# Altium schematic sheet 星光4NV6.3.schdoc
size 292 x 204 mm; Device: A_A4_1; Symbol: A_A4_1; Name: A_A4; @Project Name: 星光4N开源6.1版本; REV: 6.1; Date: 2025/11/29; Sheet: 1/1; Draw By: 韩; Company: 流浪的星星; Convert to PCB: yes; Add into BOM: yes; @Page No: 1; @Page Count: 1; @Schematic Name: 星光4NV6.1; @Board Name: 星光4NV6.1; @Update Date: 2025-11-29; @Create Time: 10:46:54; @Update Time: 11:45:03; @Page Name: 星光4奥卡; @Create Date: 2025-11-29; Border: 0; Width: 1655; Height: 1170; Region Start: 1; X Region Count: 1; Y Region Count: 1; Title Block Position: 3; Title Block: 1
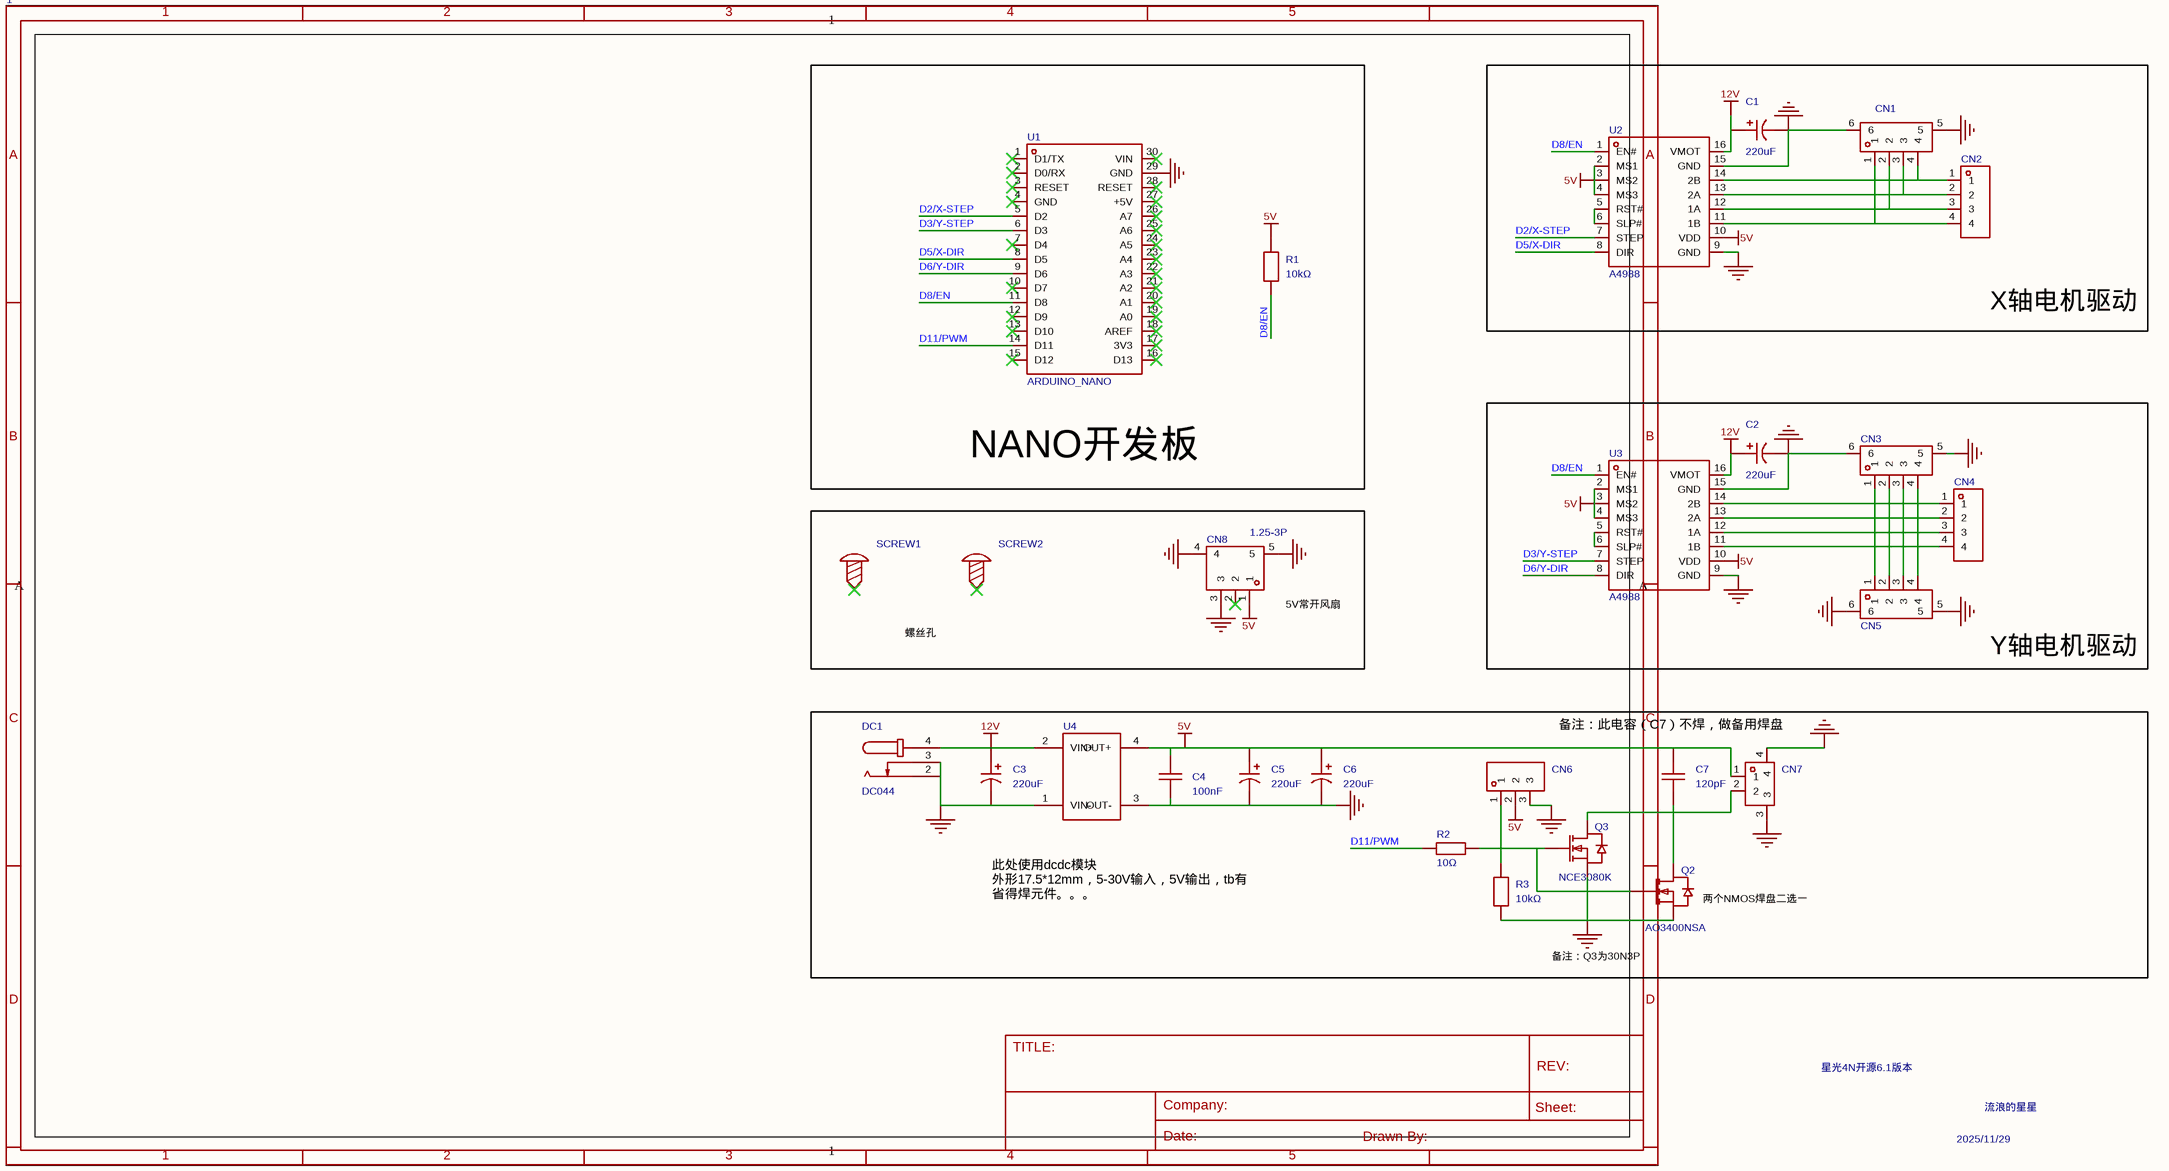
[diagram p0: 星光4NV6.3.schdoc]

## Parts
C1  220uF  [CAP-SMD_BD6.3-L6.6-W6.6-FD-1]
C2  220uF  [CAP-SMD_BD6.3-L6.6-W6.6-FD-1]
C3  220uF  [CAP-SMD_BD6.3-L6.6-W6.6-FD-1]
C4  100nF  [C1206]
C5  220uF  [CAP-SMD_BD6.3-L6.6-W6.6-FD-1]
C6  220uF  [CAP-SMD_BD6.3-L6.6-W6.6-FD-1]
C7  120pF  [C1812]
CN1  AFA07-S04ECC-00  [FPC-SMD_4P-P1.00_AFA07-S04ECC-00]  (value not drawn)
CN2  2.54-1*4P母  [HDR-TH_4P-P2.54-V-F]  (value not drawn)
CN3  10A20L04P  [FPC-SMD_4P-P1.00_10A20L04P]  (value not drawn)
CN4  2.54-1*4P母  [HDR-TH_4P-P2.54-V-F]  (value not drawn)
CN5  10A20L04P  [FPC-SMD_4P-P1.00_10A20L04P]  (value not drawn)
CN6  ZX-XH2.54-3PWZ  [HDR-TH_3P-P2.50_ZX-XH2.54-3PWZ]  (value not drawn)
CN7  ZX-XH2.54-2PWT  [CONN-SMD_2P-P2.54_MEGASTAR_ZX-XH2.54-2PWT]  (value not drawn)
CN8  1.25-3P  [CONN-SMD_1.25-3P]
DC1  DC044  [DC-IN-TH_DC044]
Q2  AO3400NSA  [SOT-23-3_L2.9-W1.3-P1.90-LS2.4-BR]
Q3  NCE3080K  [TO-252-2_L6.6-W6.1-P4.57-LS9.9-TL-CW]
R1  10kΩ  [R1206]
R2  10Ω  [R1206]
R3  10kΩ  [R1206]
SCREW1  (no value)  [M3螺丝]
SCREW2  (no value)  [M3螺丝]
U1  ARDUINO_NANO  [COMM-TH_ARDUINO_NANO]
U2  A4988  [DIP-16_L20.3-W15.2-P2.54_LS12.7_A4988]
U3  A4988  [DIP-16_L20.3-W15.2-P2.54_LS12.7_A4988]
U4  (no value)  [迷你稳压模块]

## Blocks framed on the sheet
NANO开发板: R1 U1
X轴电机驱动: C1 CN1 CN2 U2
Y轴电机驱动: C2 CN3-CN5 U3
备注：此电容（C7）不焊，做备用焊盘: C3-C7 CN6 CN7 DC1 Q2 Q3 R2 R3 U4

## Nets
5V: C4.2 C5.1 C6.1 C7.2 CN6.2 CN7.1 CN8.1 R1.2 U2.2(MS1) U2.3(MS2) U2.4(MS3) U2.10(VDD) U3.2(MS1) U3.3(MS2) U3.4(MS3) U3.10(VDD) U4.4(OUT+)
12V: C1.1 C2.1 C3.1 DC1.4 U2.16(VMOT) U3.16(VMOT) U4.2(VIN+)
GND: C1.2 C2.2 C3.2 C4.1 C5.2 C6.2 CN1.5 CN1.6 CN3.5 CN3.6 CN5.5 CN5.6 CN6.3 CN7.3 CN7.4 CN8.3 CN8.4 CN8.5 DC1.2 DC1.3 Q2.2(S) Q3.3(S) R3.1 U1.29(GND) U2.9(GND) U2.15(GND) U3.9(GND) U3.15(GND) U4.1(VIN-) U4.3(OUT-)
D2/X-STEP: U1.5(D2) U2.7(STEP)
D3/Y-STEP: U1.6(D3) U3.7(STEP)
D5/X-DIR: U1.8(D5) U2.8(DIR)
D6/Y-DIR: U1.9(D6) U3.8(DIR)
D8/EN: R1.1 U1.11(D8) U2.1(EN#) U3.1(EN#)
D11/PWM: R2.2 U1.14(D11)
NetC7_1: C7.1 CN7.2 Q2.3(D) Q3.2(D)
NetCN1_1: CN1.1 CN2.4 U2.11(1B)
NetCN1_2: CN1.2 CN2.3 U2.12(1A)
NetCN1_3: CN1.3 CN2.2 U2.13(2A)
NetCN1_4: CN1.4 CN2.1 U2.14(2B)
NetCN3_1: CN3.1 CN4.4 CN5.1 U3.11(1B)
NetCN3_2: CN3.2 CN4.3 CN5.2 U3.12(1A)
NetCN3_3: CN3.3 CN4.2 CN5.3 U3.13(2A)
NetCN3_4: CN3.4 CN4.1 CN5.4 U3.14(2B)
NetCN6_1: CN6.1 Q2.1(G) Q3.1(G) R2.1 R3.2
NetU2_5: U2.5(RST#) U2.6(SLP#)
NetU3_5: U3.5(RST#) U3.6(SLP#)

Not connected (* = marked no-connect by the designer): CN8 2*; SCREW1 1*; SCREW2 1*; U1 1(D1/TX)* 2(D0/RX)* 3(RESET)* 4(GND)* 7(D4)* 10(D7)* 12(D9)* 13(D10)* 15(D12)* 16(D13)* 17(3V3)* 18(AREF)* 19(A0)* 20(A1)* 21(A2)* 22(A3)* 23(A4)* 24(A5)* 25(A6)* 26(A7)* 27(+5V)* 28(RESET)* 30(VIN)*

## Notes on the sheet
- (near CN8) 5V常开风扇
- 螺丝孔
- 此处使用dcdc模块
  外形17.5*12mm，5-30V输入，5V输出，tb有
  省得焊元件。。。
- (near Q2) 两个NMOS焊盘二选一
- 备注：Q3为30N3P

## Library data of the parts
C1-C3 C5 C6 = JVJ16V220M6x8: 容值:220uF;精度:±20%;额定电压:16V;纹波电流:110mA@120Hz;; Manufacturer: 捷而瑞; AddInBom: yes; ModelId: 041333f082e2432d92aae8a67d233574; ModelTransform: 299.212,259.842,0,0,0,0,0,0,0; Tolerance: ±20%; Voltage Rating: 16V; Lifetime: 2000hrs@105℃
C4 = CL31B104KBCNNNC: 容值:100nF;精度:±10%;额定电压:50V;温度系数:X7R;; Manufacturer: SAMSUNG(三星); AddInBom: yes; ModelId: e4be705b945545a48e666415e3682bd8; ModelName: C1206_L3.2-W1.6-H1.3; ModelTransform: 125.984,62.992,0,0,0,0,0,0,0; Tolerance: ±10%; Voltage Rating: 50V; Temperature Coefficient: X7R
C7 = FV43N121J302ECG: 容值:120pF;精度:±5%;额定电压:3kV;温度系数:C0G;; Manufacturer: PSA(信昌电陶); AddInBom: yes; ModelId: 654205cbd64044c4b833fe7af5979bc9; ModelName: C1812_L4.5-W3.2-H2.6; ModelTransform: 177.165,125.984,0,0,0,0,0.0005,0,0; Tolerance: ±5%; Voltage Rating: 3kV; Temperature Coefficient: C0G
CN1 = AFA07-S04ECC-00: 锁定特性:抽屉式;触点类型:上接;触点数量:4P;间距:1mm;安装类型:卧贴;; Manufacturer: JS(钜硕电子); Symbol: FPCPull type Pick up H3.0mm; AddInBom: yes; ModelId: eb2037eadb4f4f60bc0cbc983aef8acd; ModelName: FPC-SMD_4P-P1.00_L11.0-W6.9-H2.5-AFA07-S04ECC-00; ModelTransform: 433.07,271.653,0,0,0,0,0,-76.773,0; Locking Feature: 抽屉式; Number of Contacts: 4P; Pitch: 1mm; FFC, FCB Thickness: 0.3mm
CN2 CN4 = 2.54-1*4P母: 插孔结构:1x4P;间距:2.54mm;行距:-;圆孔/方孔:方孔;安装类型:直插;排数:单排;总孔位数:4P;额定电流:3A;额定电压:-;插孔方向:顶部;塑高:-;触头材质:青铜;触头镀层:-;工作温度范围:-40℃~+105℃;焊接温度(最大值):-;; Manufacturer: BOOMELE(博穆精密); AddInBom: yes; ModelId: d187812051054f85879fcaa51a310d8e; ModelTransform: 419.6842,98.464,0,0,0,0,0,0,-118.11; Holes Structure: 1x4P; Pitch: 2.54mm; Circular Hole / Square Hole: 方孔; Number of Holes: 4P; Current Rating (Max): 3A; Holes Direction: 顶部
CN3 CN5 = 10A20L04P: 锁定特性:翻盖式;触点类型:下接;触点数量:4P;间距:1mm;; Manufacturer: HanElectricity(瀚源); AddInBom: yes; ModelId: 74aa4c8d5552434e99fa2d5862a4320d; ModelTransform: 354.7237,234.2515,0,0,0,0,0,-62.165,0; Locking Feature: 翻盖式; Number of Contacts: 4P; Pitch: 1mm
CN6 = ZX-XH2.54-3PWZ: 插针结构:1x3P;间距:2.5mm;安装方式:弯插;参考系列:XH;总PIN数:3P;排数:1;每排PIN数:3;行距:-;额定电流:3A;触头材质:黄铜;触头镀层:锡;工作温度:-25℃~+85℃;; Manufacturer: Megastar(兆星); AddInBom: yes; ModelId: a145bc240201499fa30f39acf7784329; ModelTransform: 394.094,300.58995,0,0,0,0,-0.005,-137.792,-133.858; Pins Structure: 1x3P; Pitch: 2.5mm; Reference Series: XH; Number of PINs Per Row: 3; Current Rating: 3A; Voltage Rating: 250V; Plastic Material: PA66; Flame Retardant Rating: UL94V-0; Z-Height of the Board: 5.9mm; X-Length of Bottom Edge on Board (Spacing Line): 10mm; Y-Width of Bottom Edge on Board: 7.32mm
CN7 = ZX-XH2.54-2PWT: 插针结构:1x2P;间距:2.5mm;安装方式:卧贴;参考系列:XH;总PIN数:2P;排数:1;每排PIN数:2;行距:-;额定电流:3A;触头材质:黄铜;触头镀层:锡;工作温度:-25℃~+85℃;; Manufacturer: Megastar(兆星); AddInBom: yes; ModelId: 905258e72c284f268702918f5ed0d447; ModelTransform: 393.7,413.385,0,0,0,0,0,0.001,0; Pins Structure: 1x2P; Pitch: 2.5mm; Reference Series: XH; Number of PINs Per Row: 2; Current Rating: 3A; Voltage Rating: 250V; Supplementary Features: 辅助焊脚; Z-Height of the Board: 6.2mm; X-Length of Bottom Edge on Board (Spacing Line): 10mm; Y-Width of Bottom Edge on Board: 10.5mm
CN8 = 1.25-3P: 插针结构:1x3P;间距:1.25mm;安装方式:卧贴;参考系列:PicoBlade(MX 1.25);总PIN数:3P;排数:1;每排PIN数:3;行距:-;额定电流:1A;触头材质:磷青铜;触头镀层:锡;工作温度:-25℃~+85℃;; Manufacturer: SHOU HAN(首韩); AddInBom: yes; ModelId: 0317240b465f49dc9026c4522c6e57b4; ModelName: CONN-SMD_MX1.25-WS-3P; ModelTransform: 350.393,204.3303,0,0,0,0,0,-30.709,0; Pins Structure: 1x3P; Pitch: 1.25mm; Number of PINs Per Row: 3; Current Rating: 1A; Voltage Rating: 125V; Plastic Material: LCP; Flame Retardant Rating: UL94V-0
DC1 = DC044: 连接器类型:DC电源插座;安装方式:弯插;触点内径:2mm;触点外径:6mm;额定电流:1A;额定电压:30V;工作温度范围:-25℃~+70℃;; Manufacturer: SHOU HAN(首韩); AddInBom: yes; ModelId: b408fe5c839c4e2494e641f3d5bfb7bc; ModelTransform: 452.755,374.015,0,0,0,0,-173.858,7.872,-118.11; Connector Type: DC电源插座; Inside Contact Diameter: 2mm; Outside Contact Diameter: 6mm; Current Rating (Max): 1A; Voltage Rating (Max): 30V
Q2 = AO3400NSA: 类型:1个N沟道;漏源电压(Vdss):30V;连续漏极电流(Id):5.8A;导通电阻(RDS(on)@Vgs,Id):28mΩ@10V,5.8A;功率(Pd):1.2W;阈值电压(Vgs(th)@Id):1.4V@250uA;; Manufacturer: DOWO(东沃); AddInBom: yes; ModelId: c62791f0466c4ae2a892c056b845b0ca; ModelName: SOT-23-3P_L2.9-W1.3-H1.0-LS2.4-P0.95; ModelTransform: 98.425,114.173,0,180,0,0,0.0005,-0.0005,0; Type: 1个N沟道; Drain Source Voltage (Vdss): 30V; Power Dissipation (Pd): 1.2W
Q3 = NCE3080K: 类型:1个N沟道;漏源电压(Vdss):30V;连续漏极电流(Id):80A;导通电阻(RDS(on)):6.5mΩ@10V,80A;耗散功率(Pd):83W;阈值电压(Vgs(th)):1.6V;; Manufacturer: NCE(无锡新洁能); AddInBom: yes; ModelId: ce57f84d66384067af8a68020b6de06d; ModelName: TO-252-2L-3P_L6.6-W6.1-H2.3-LS10.1-P4.6; ModelTransform: 259.842,390.52442,0,270,0,0,38.027,-0.598,0; Type: 1个N沟道; Drain to Source Voltage: 30V; Pd - Power Dissipation: 83W; Gate Threshold Voltage (Vgs(th)@Id): 1.6V; Gate Charge(Qg): 51nC@10V; Input Capacitance(Ciss@Vds): 2.33nF@15V; Reverse Transfer Capacitance (Crss@Vds): 230pF@15V
R1 R3 = FRR1206J103 TS: 电阻类型:厚膜电阻;阻值:10kΩ;精度:±5%;功率:250mW;工作电压:200V;温度系数:±100ppm/℃;; Manufacturer: FOJAN(富捷); AddInBom: yes; ModelId: 89a1f13db2384da588040e0b3c55bf66; ModelName: R1206_L3.2-W1.6-H0.6; ModelTransform: 125.984,62.992,0,0,0,0,0,0,0; Tolerance: ±5%; Power(Watts): 250mW; Voltage-Supply(Max): 200V
R2 = 1206W4F100JT5E: 电阻类型:厚膜电阻;阻值:10Ω;精度:±1%;功率:250mW;工作电压:200V;温度系数:±400ppm/℃;; Manufacturer: UNI-ROYAL(厚声); AddInBom: yes; ModelId: 89a1f13db2384da588040e0b3c55bf66; ModelName: R1206_L3.2-W1.6-H0.6; ModelTransform: 125.984,62.992,0,0,0,0,0,0,0; Tolerance: ±1%; Power(Watts): 250mW; Voltage-Supply(Max): 200V
SCREW1 SCREW2 = M3螺丝: ConvertToPcb: yes; SymbolName: 螺丝孔
U1 = ARDUINO_NANO: AddInBom: yes; ModelId: 569460a3ee974a868db0f4d8fd87e38b; ModelTransform: 699.9986,1784.14604,0,270,0,0,-42.323,0,-137.795
U2 U3 = A4988: AddInBom: yes; ModelId: 91b5bbb4c7ad4d72991c4bfd5544d532; ModelTransform: 599.9988,799.998,0,0,0,0,0,0,-196.85
U4 = 迷你降压模块: AddInBom: yes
